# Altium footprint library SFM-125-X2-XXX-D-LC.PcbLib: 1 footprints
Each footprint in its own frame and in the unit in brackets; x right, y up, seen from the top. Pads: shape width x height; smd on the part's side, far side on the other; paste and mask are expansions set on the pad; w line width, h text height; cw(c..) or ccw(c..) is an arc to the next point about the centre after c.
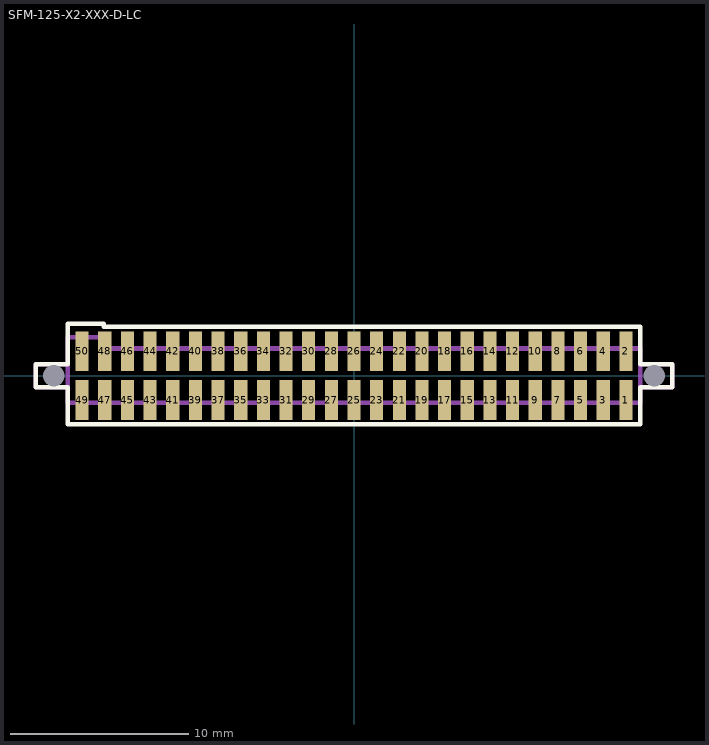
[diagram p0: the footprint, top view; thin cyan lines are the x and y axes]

## SFM-125-X2-XXX-D-LC [mil]
height 180
pads (52):
  rect 29x87.5 smd mask+2: 1(600,-53.75) 2(600,53.75) 3(550,-53.75) 4(550,53.75) 5(500,-53.75) 6(500,53.75) 7(450,-53.75) 8(450,53.75) 9(400,-53.75) 10(400,53.75) 11(350,-53.75) 12(350,53.75) 13(300,-53.75) 14(300,53.75) 15(250,-53.75) 16(250,53.75) 17(200,-53.75) 18(200,53.75) 19(150,-53.75) 20(150,53.75) 21(100,-53.75) 22(100,53.75) 23(50,-53.75) 24(50,53.75) 25(0,-53.75) 26(0,53.75) 27(-50,-53.75) 28(-50,53.75) 29(-100,-53.75) 30(-100,53.75) 31(-150,-53.75) 32(-150,53.75) 33(-200,-53.75) 34(-200,53.75) 35(-250,-53.75) 36(-250,53.75) 37(-300,-53.75) 38(-300,53.75) 39(-350,-53.75) 40(-350,53.75) 41(-400,-53.75) 42(-400,53.75) 43(-450,-53.75) 44(-450,53.75) 45(-500,-53.75) 46(-500,53.75) 47(-550,-53.75) 48(-550,53.75) 49(-600,-53.75) 50(-600,53.75)
  round 0 hole 47 unplated: 51(662.5,0) 52(-662.5,0)
Top Overlay:
  lines w10: -702,-25 -702,25 -632,25 -632,115 -552,115 -552,107.5 632,107.5 632,25 702,25 702,-25 632,-25 632,-107.5 -632,-107.5 -632,-25 -702,-25
Mechanical 1:
  lines w10: -632,-25 -702,-25 -702,25 -632,25 ; 632,-25 702,-25 702,25 632,25 ; -632,-60 -632,85 -552,85 -552,60 632,60 632,-60 -632,-60
  text "J1" at -17.57,-18 h30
